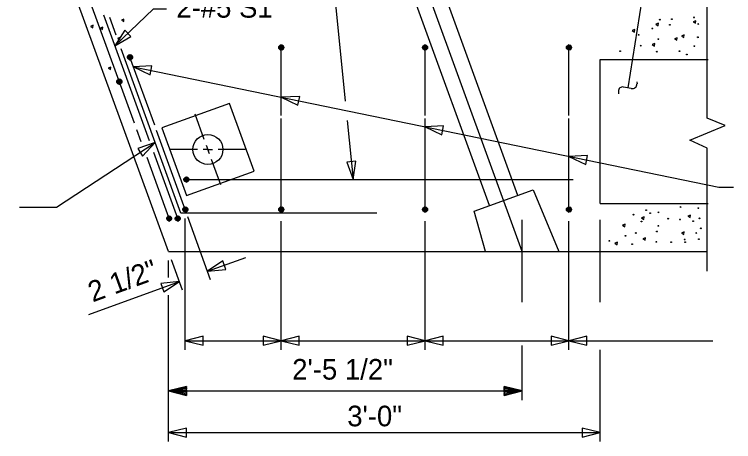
# Model space of a CAD drawing. Extents: x -408 to -23, y -15 to 117.
# Drawn here: x -115.169 to -110.17, y 40.166 to 43.132 of the extents above; entities that cross this region are included whole.
import ezdxf

# ---------------------------------------------------------------- set-up
doc = ezdxf.new("R2010")
doc.units = 0
for name, color, linetype in [('Arrowhead Terminators CELL', 7, 'Continuous'), ('Dimension Lines', 7, 'Continuous'), ('Mis Center Lines', 7, 'Continuous'), ('Rebar Lines', 7, 'Continuous'), ('Sup Concrete Girder Lines', 7, 'Continuous'), ('Sup Cored Slab Unit', 7, 'Continuous'), ('Text', 7, 'Continuous')]:
    doc.layers.add(name, color=color, linetype=linetype)

msp = doc.modelspace()

# ---------------------------------------------------------------- linework, layer by layer
at = {"layer": 'Arrowhead Terminators CELL'}
for points in [[(-114.471, 42.9146), (-114.359, 42.9782), (-114.402, 43.0235)], [(-114.3417, 42.7692), (-114.2256, 42.7134), (-114.213, 42.7746)], [(-113.3141, 42.5577), (-113.198, 42.5019), (-113.1854, 42.5632)], [(-112.3141, 42.352), (-112.198, 42.2962), (-112.1854, 42.3574)], [(-114.19, 42.2424), (-114.3117, 42.2), (-114.2774, 42.1478)], [(-111.3141, 42.1462), (-111.198, 42.0904), (-111.1854, 42.1516)], [(-112.8146, 41.9859), (-112.7959, 42.1134), (-112.8581, 42.1072)], [(-113.8264, 41.3484), (-113.6982, 41.3618), (-113.7196, 41.4206)], [(-114.0221, 41.2772), (-114.1502, 41.2638), (-114.1289, 41.2051)], [(-113.9808, 40.8667), (-113.8558, 40.8355), (-113.8558, 40.898)], [(-113.3141, 40.8667), (-113.4391, 40.898), (-113.4391, 40.8355)], [(-113.3141, 40.8667), (-113.1891, 40.8355), (-113.1891, 40.898)], [(-112.3141, 40.8667), (-112.4391, 40.898), (-112.4391, 40.8355)], [(-112.3141, 40.8667), (-112.1891, 40.8355), (-112.1891, 40.898)], [(-111.3141, 40.8667), (-111.4391, 40.898), (-111.4391, 40.8355)], [(-111.3141, 40.8667), (-111.1891, 40.8355), (-111.1891, 40.898)], [(-114.098, 40.229), (-113.973, 40.1978), (-113.973, 40.2603)], [(-111.098, 40.229), (-111.223, 40.2603), (-111.223, 40.1978)]]:
    msp.add_lwpolyline(points, close=True, dxfattribs=at)
at = {"layer": 'Dimension Lines'}
for p, q in [((-112.9761, 43.6051), (-112.8687, 42.5288)), ((-110.8417, 42.6647), (-110.8415, 42.6509)), ((-110.9699, 42.5983), (-110.9704, 42.58)), ((-110.8812, 42.6188), (-110.9357, 42.6275)), ((-113.8488, 42.2631), (-113.913, 42.4392)), ((-112.8554, 42.3948), (-112.8146, 41.9859)), ((-113.8954, 42.1945), (-114.0829, 42.1944)), ((-113.5647, 42.1944), (-113.7523, 42.1944)), ((-113.7347, 41.9496), (-113.7989, 42.1258)), ((-113.9808, 40.8037), (-113.9808, 41.715)), ((-113.805, 41.2897), (-113.9637, 41.7261)), ((-113.3141, 40.8037), (-113.3141, 41.6974)), ((-112.3141, 40.8037), (-112.3141, 41.6974)), ((-111.6396, 41.134), (-111.6396, 41.7067)), ((-111.3141, 40.8037), (-111.3141, 41.6974)), ((-111.098, 41.134), (-111.098, 41.7067)), ((-113.8264, 41.3484), (-113.561, 41.4451)), ((-114.098, 41.3057), (-114.098, 41.4234)), ((-114.0007, 41.2184), (-114.0766, 41.4271)), ((-114.6521, 41.0479), (-114.0221, 41.2772)), ((-114.098, 40.166), (-114.098, 41.1822)), ((-113.9808, 40.8667), (-113.3141, 40.8667)), ((-113.3141, 40.8667), (-112.3141, 40.8667)), ((-112.3141, 40.8667), (-111.3141, 40.8667)), ((-111.3141, 40.8667), (-110.3141, 40.8667)), ((-111.6396, 40.4548), (-111.6396, 40.8332)), ((-111.098, 40.166), (-111.098, 40.8042)), ((-114.098, 40.5178), (-111.6396, 40.5178)), ((-114.098, 40.229), (-111.098, 40.229))]:
    msp.add_line(p, q, dxfattribs=at)
for points in [[(-110.9035, 42.6224), (-110.7245, 43.7456), (-110.8716, 43.7456)], [(-114.471, 42.9146), (-114.2026, 43.1701), (-114.1117, 43.1701)], [(-114.3417, 42.7692), (-110.272, 41.9318), (-110.17, 41.9318)], [(-115.1321, 41.7927), (-114.8761, 41.7927), (-114.19, 42.2424)], [(-113.8347, 42.2239), (-113.8238, 42.1944), (-113.8554, 42.1943)], [(-113.8128, 42.1647), (-113.8235, 42.1942), (-113.7921, 42.1943)], [(-113.973, 40.5178), (-113.973, 40.5115), (-114.098, 40.5178), (-113.973, 40.5053), (-113.973, 40.499), (-114.098, 40.5178), (-113.973, 40.4928), (-113.973, 40.4865), (-114.098, 40.5178), (-113.973, 40.549), (-113.973, 40.5428), (-114.098, 40.5178), (-113.973, 40.5365), (-113.973, 40.5303), (-114.098, 40.5178), (-113.973, 40.524), (-113.973, 40.4865), (-113.973, 40.549), (-114.098, 40.5178), (-113.973, 40.4865)], [(-111.7646, 40.5178), (-111.7646, 40.524), (-111.6396, 40.5178), (-111.7646, 40.5303), (-111.7646, 40.5365), (-111.6396, 40.5178), (-111.7646, 40.5428), (-111.7646, 40.549), (-111.6396, 40.5178), (-111.7646, 40.4865), (-111.7646, 40.4928), (-111.6396, 40.5178), (-111.7646, 40.499), (-111.7646, 40.5053), (-111.6396, 40.5178), (-111.7646, 40.5115), (-111.7646, 40.549), (-111.7646, 40.4865), (-111.6396, 40.5178), (-111.7646, 40.549)]]:
    msp.add_lwpolyline(points, dxfattribs=at)
for centre, radius, start, end in [((-110.8728, 42.6487), 0.0311, 254.3783, 4.1772), ((-110.9422, 42.6008), 0.0276, 76.8232, 185.1088)]:
    msp.add_arc(centre, radius, start, end, dxfattribs=at)
at = {"layer": 'Mis Center Lines'}
msp.add_line((-111.6396, 41.4859), (-112.79, 44.6464), dxfattribs=at)
at = {"layer": 'Rebar Lines'}
for p, q in [((-114.3337, 42.3769), (-114.6366, 43.209)), ((-114.2294, 42.2549), (-114.5465, 43.1261)), ((-114.461, 42.987), (-114.5057, 43.1097)), ((-114.0113, 41.7515), (-114.4267, 42.8928)), ((-113.3141, 42.4309), (-113.3141, 42.9025)), ((-112.3141, 42.4309), (-112.3141, 42.9025)), ((-111.3141, 42.4309), (-111.3141, 42.9025)), ((-114.1935, 42.3621), (-114.3656, 42.8347)), ((-113.3141, 41.7775), (-113.3141, 42.4091)), ((-112.3141, 41.7775), (-112.3141, 42.4091)), ((-111.3141, 41.7775), (-111.3141, 42.4091)), ((-114.2868, 42.2482), (-114.317, 42.3312)), ((-113.9808, 41.7775), (-114.1806, 42.3264)), ((-114.0928, 41.715), (-114.2467, 42.138)), ((-114.033, 41.715), (-114.2, 42.1738)), ((-113.9728, 41.9859), (-111.2853, 41.9859)), ((-112.6503, 41.7515), (-114.0113, 41.7515))]:
    msp.add_line(p, q, dxfattribs=at)
for points in [[(-113.3317, 42.9025), (-113.3304, 42.9092), (-113.3266, 42.915), (-113.3209, 42.9188), (-113.3141, 42.9201), (-113.3074, 42.9188), (-113.3017, 42.915), (-113.2979, 42.9093), (-113.2965, 42.9025), (-113.2979, 42.8958), (-113.3017, 42.8901), (-113.3074, 42.8862), (-113.3141, 42.8849), (-113.3209, 42.8862), (-113.3266, 42.89), (-113.3304, 42.8957), (-113.3317, 42.9025), (-113.3141, 42.9025), (-113.2965, 42.9025), (-113.2979, 42.9093), (-113.3141, 42.9025), (-113.3017, 42.915), (-113.3074, 42.9188), (-113.3141, 42.9025), (-113.3141, 42.9201), (-113.3209, 42.9188), (-113.3141, 42.9025), (-113.3266, 42.915), (-113.3304, 42.9092), (-113.3141, 42.9025), (-113.3304, 42.8957), (-113.3266, 42.89), (-113.3141, 42.9025), (-113.3209, 42.8862), (-113.3141, 42.8849), (-113.3141, 42.9025), (-113.3074, 42.8862), (-113.3017, 42.8901), (-113.3141, 42.9025), (-113.2979, 42.8958)], [(-112.3317, 42.9025), (-112.3304, 42.9092), (-112.3266, 42.915), (-112.3209, 42.9188), (-112.3141, 42.9201), (-112.3074, 42.9188), (-112.3017, 42.915), (-112.2979, 42.9093), (-112.2965, 42.9025), (-112.2979, 42.8958), (-112.3017, 42.8901), (-112.3074, 42.8862), (-112.3141, 42.8849), (-112.3209, 42.8862), (-112.3266, 42.89), (-112.3304, 42.8957), (-112.3317, 42.9025), (-112.3141, 42.9025), (-112.2965, 42.9025), (-112.2979, 42.9093), (-112.3141, 42.9025), (-112.3017, 42.915), (-112.3074, 42.9188), (-112.3141, 42.9025), (-112.3141, 42.9201), (-112.3209, 42.9188), (-112.3141, 42.9025), (-112.3266, 42.915), (-112.3304, 42.9092), (-112.3141, 42.9025), (-112.3304, 42.8957), (-112.3266, 42.89), (-112.3141, 42.9025), (-112.3209, 42.8862), (-112.3141, 42.8849), (-112.3141, 42.9025), (-112.3074, 42.8862), (-112.3017, 42.8901), (-112.3141, 42.9025), (-112.2979, 42.8958)], [(-111.3317, 42.9025), (-111.3304, 42.9092), (-111.3266, 42.915), (-111.3209, 42.9188), (-111.3141, 42.9201), (-111.3074, 42.9188), (-111.3017, 42.915), (-111.2979, 42.9093), (-111.2965, 42.9025), (-111.2979, 42.8958), (-111.3017, 42.8901), (-111.3074, 42.8862), (-111.3141, 42.8849), (-111.3209, 42.8862), (-111.3266, 42.89), (-111.3304, 42.8957), (-111.3317, 42.9025), (-111.3141, 42.9025), (-111.2965, 42.9025), (-111.2979, 42.9093), (-111.3141, 42.9025), (-111.3017, 42.915), (-111.3074, 42.9188), (-111.3141, 42.9025), (-111.3141, 42.9201), (-111.3209, 42.9188), (-111.3141, 42.9025), (-111.3266, 42.915), (-111.3304, 42.9092), (-111.3141, 42.9025), (-111.3304, 42.8957), (-111.3266, 42.89), (-111.3141, 42.9025), (-111.3209, 42.8862), (-111.3141, 42.8849), (-111.3141, 42.9025), (-111.3074, 42.8862), (-111.3017, 42.8901), (-111.3141, 42.9025), (-111.2979, 42.8958)], [(-114.3829, 42.8317), (-114.3828, 42.8385), (-114.3801, 42.8448), (-114.3751, 42.8496), (-114.3687, 42.852), (-114.3618, 42.8519), (-114.3555, 42.8491), (-114.3507, 42.8442), (-114.3482, 42.8378), (-114.3484, 42.8309), (-114.3512, 42.8246), (-114.3561, 42.8199), (-114.3625, 42.8174), (-114.3694, 42.8175), (-114.3757, 42.8203), (-114.3805, 42.8252), (-114.3829, 42.8317), (-114.3656, 42.8347), (-114.3482, 42.8378), (-114.3507, 42.8442), (-114.3656, 42.8347), (-114.3555, 42.8491), (-114.3618, 42.8519), (-114.3656, 42.8347), (-114.3687, 42.852), (-114.3751, 42.8496), (-114.3656, 42.8347), (-114.3801, 42.8448), (-114.3828, 42.8385), (-114.3656, 42.8347), (-114.3805, 42.8252), (-114.3757, 42.8203), (-114.3656, 42.8347), (-114.3694, 42.8175), (-114.3625, 42.8174), (-114.3656, 42.8347), (-114.3561, 42.8199), (-114.3512, 42.8246), (-114.3656, 42.8347), (-114.3484, 42.8309)], [(-114.456, 42.6623), (-114.4559, 42.6691), (-114.4531, 42.6754), (-114.4481, 42.6802), (-114.4417, 42.6827), (-114.4349, 42.6826), (-114.4285, 42.6798), (-114.4238, 42.6748), (-114.4213, 42.6684), (-114.4215, 42.6615), (-114.4242, 42.6552), (-114.4292, 42.6504), (-114.4356, 42.6479), (-114.4425, 42.6481), (-114.4488, 42.6508), (-114.4535, 42.6558), (-114.456, 42.6623), (-114.4387, 42.6653), (-114.4213, 42.6684), (-114.4238, 42.6748), (-114.4387, 42.6653), (-114.4285, 42.6798), (-114.4349, 42.6826), (-114.4387, 42.6653), (-114.4417, 42.6827), (-114.4481, 42.6802), (-114.4387, 42.6653), (-114.4531, 42.6754), (-114.4559, 42.6691), (-114.4387, 42.6653), (-114.4535, 42.6558), (-114.4488, 42.6508), (-114.4387, 42.6653), (-114.4425, 42.6481), (-114.4356, 42.6479), (-114.4387, 42.6653), (-114.4292, 42.6504), (-114.4242, 42.6552), (-114.4387, 42.6653), (-114.4215, 42.6615)], [(-113.9901, 41.9828), (-113.99, 41.9897), (-113.9872, 41.996), (-113.9823, 42.0008), (-113.9758, 42.0032), (-113.969, 42.0031), (-113.9627, 42.0003), (-113.958, 41.9954), (-113.9555, 41.989), (-113.9556, 41.9821), (-113.9584, 41.9758), (-113.9633, 41.971), (-113.9697, 41.9685), (-113.9766, 41.9687), (-113.9829, 41.9714), (-113.9877, 41.9764), (-113.9901, 41.9828), (-113.9728, 41.9859), (-113.9555, 41.989), (-113.958, 41.9954), (-113.9728, 41.9859), (-113.9627, 42.0003), (-113.969, 42.0031), (-113.9728, 41.9859), (-113.9758, 42.0032), (-113.9823, 42.0008), (-113.9728, 41.9859), (-113.9872, 41.996), (-113.99, 41.9897), (-113.9728, 41.9859), (-113.9877, 41.9764), (-113.9829, 41.9714), (-113.9728, 41.9859), (-113.9766, 41.9687), (-113.9697, 41.9685), (-113.9728, 41.9859), (-113.9633, 41.971), (-113.9584, 41.9758), (-113.9728, 41.9859), (-113.9556, 41.9821)], [(-113.9981, 41.7744), (-113.998, 41.7813), (-113.9953, 41.7876), (-113.9903, 41.7924), (-113.9839, 41.7949), (-113.977, 41.7948), (-113.9707, 41.7919), (-113.966, 41.787), (-113.9634, 41.7806), (-113.9637, 41.7737), (-113.9664, 41.7674), (-113.9713, 41.7626), (-113.9777, 41.7601), (-113.9846, 41.7603), (-113.9909, 41.763), (-113.9957, 41.768), (-113.9981, 41.7744), (-113.9808, 41.7775), (-113.9634, 41.7806), (-113.966, 41.787), (-113.9808, 41.7775), (-113.9707, 41.7919), (-113.977, 41.7948), (-113.9808, 41.7775), (-113.9839, 41.7949), (-113.9903, 41.7924), (-113.9808, 41.7775), (-113.9953, 41.7876), (-113.998, 41.7813), (-113.9808, 41.7775), (-113.9957, 41.768), (-113.9909, 41.763), (-113.9808, 41.7775), (-113.9846, 41.7603), (-113.9777, 41.7601), (-113.9808, 41.7775), (-113.9713, 41.7626), (-113.9664, 41.7674), (-113.9808, 41.7775), (-113.9637, 41.7737)], [(-113.3317, 41.7775), (-113.3304, 41.7842), (-113.3266, 41.79), (-113.3209, 41.7938), (-113.3141, 41.7951), (-113.3074, 41.7938), (-113.3017, 41.79), (-113.2979, 41.7843), (-113.2965, 41.7775), (-113.2979, 41.7708), (-113.3017, 41.7651), (-113.3074, 41.7612), (-113.3141, 41.7599), (-113.3209, 41.7612), (-113.3266, 41.765), (-113.3304, 41.7707), (-113.3317, 41.7775), (-113.3141, 41.7775), (-113.2965, 41.7775), (-113.2979, 41.7843), (-113.3141, 41.7775), (-113.3017, 41.79), (-113.3074, 41.7938), (-113.3141, 41.7775), (-113.3141, 41.7951), (-113.3209, 41.7938), (-113.3141, 41.7775), (-113.3266, 41.79), (-113.3304, 41.7842), (-113.3141, 41.7775), (-113.3304, 41.7707), (-113.3266, 41.765), (-113.3141, 41.7775), (-113.3209, 41.7612), (-113.3141, 41.7599), (-113.3141, 41.7775), (-113.3074, 41.7612), (-113.3017, 41.7651), (-113.3141, 41.7775), (-113.2979, 41.7708)], [(-112.3317, 41.7775), (-112.3304, 41.7842), (-112.3266, 41.79), (-112.3209, 41.7938), (-112.3141, 41.7951), (-112.3074, 41.7938), (-112.3017, 41.79), (-112.2979, 41.7843), (-112.2965, 41.7775), (-112.2979, 41.7708), (-112.3017, 41.7651), (-112.3074, 41.7612), (-112.3141, 41.7599), (-112.3209, 41.7612), (-112.3266, 41.765), (-112.3304, 41.7707), (-112.3317, 41.7775), (-112.3141, 41.7775), (-112.2965, 41.7775), (-112.2979, 41.7843), (-112.3141, 41.7775), (-112.3017, 41.79), (-112.3074, 41.7938), (-112.3141, 41.7775), (-112.3141, 41.7951), (-112.3209, 41.7938), (-112.3141, 41.7775), (-112.3266, 41.79), (-112.3304, 41.7842), (-112.3141, 41.7775), (-112.3304, 41.7707), (-112.3266, 41.765), (-112.3141, 41.7775), (-112.3209, 41.7612), (-112.3141, 41.7599), (-112.3141, 41.7775), (-112.3074, 41.7612), (-112.3017, 41.7651), (-112.3141, 41.7775), (-112.2979, 41.7708)], [(-111.3317, 41.7775), (-111.3304, 41.7842), (-111.3266, 41.79), (-111.3209, 41.7938), (-111.3141, 41.7951), (-111.3074, 41.7938), (-111.3017, 41.79), (-111.2979, 41.7843), (-111.2965, 41.7775), (-111.2979, 41.7708), (-111.3017, 41.7651), (-111.3074, 41.7612), (-111.3141, 41.7599), (-111.3209, 41.7612), (-111.3266, 41.765), (-111.3304, 41.7707), (-111.3317, 41.7775), (-111.3141, 41.7775), (-111.2965, 41.7775), (-111.2979, 41.7843), (-111.3141, 41.7775), (-111.3017, 41.79), (-111.3074, 41.7938), (-111.3141, 41.7775), (-111.3141, 41.7951), (-111.3209, 41.7938), (-111.3141, 41.7775), (-111.3266, 41.79), (-111.3304, 41.7842), (-111.3141, 41.7775), (-111.3304, 41.7707), (-111.3266, 41.765), (-111.3141, 41.7775), (-111.3209, 41.7612), (-111.3141, 41.7599), (-111.3141, 41.7775), (-111.3074, 41.7612), (-111.3017, 41.7651), (-111.3141, 41.7775), (-111.2979, 41.7708)], [(-114.1101, 41.7119), (-114.11, 41.7188), (-114.1072, 41.7251), (-114.1023, 41.7299), (-114.0958, 41.7324), (-114.089, 41.7323), (-114.0827, 41.7294), (-114.078, 41.7245), (-114.0755, 41.7181), (-114.0756, 41.7112), (-114.0784, 41.7049), (-114.0833, 41.7001), (-114.0897, 41.6976), (-114.0966, 41.6978), (-114.1029, 41.7005), (-114.1077, 41.7055), (-114.1101, 41.7119), (-114.0928, 41.715), (-114.0755, 41.7181), (-114.078, 41.7245), (-114.0928, 41.715), (-114.0827, 41.7294), (-114.089, 41.7323), (-114.0928, 41.715), (-114.0958, 41.7324), (-114.1023, 41.7299), (-114.0928, 41.715), (-114.1072, 41.7251), (-114.11, 41.7188), (-114.0928, 41.715), (-114.1077, 41.7055), (-114.1029, 41.7005), (-114.0928, 41.715), (-114.0966, 41.6978), (-114.0897, 41.6976), (-114.0928, 41.715), (-114.0833, 41.7001), (-114.0784, 41.7049), (-114.0928, 41.715), (-114.0756, 41.7112)], [(-114.0504, 41.712), (-114.0502, 41.7188), (-114.0475, 41.7251), (-114.0425, 41.7299), (-114.036, 41.7324), (-114.0292, 41.7323), (-114.0229, 41.7294), (-114.0182, 41.7245), (-114.0157, 41.7181), (-114.0158, 41.7113), (-114.0186, 41.705), (-114.0235, 41.7002), (-114.03, 41.6977), (-114.0368, 41.6978), (-114.0431, 41.7006), (-114.0479, 41.7055), (-114.0504, 41.712), (-114.033, 41.715), (-114.0157, 41.7181), (-114.0182, 41.7245), (-114.033, 41.715), (-114.0229, 41.7294), (-114.0292, 41.7323), (-114.033, 41.715), (-114.036, 41.7324), (-114.0425, 41.7299), (-114.033, 41.715), (-114.0475, 41.7251), (-114.0502, 41.7188), (-114.033, 41.715), (-114.0479, 41.7055), (-114.0431, 41.7006), (-114.033, 41.715), (-114.0368, 41.6978), (-114.03, 41.6977), (-114.033, 41.715), (-114.0235, 41.7002), (-114.0186, 41.705), (-114.033, 41.715), (-114.0158, 41.7113)]]:
    msp.add_lwpolyline(points, dxfattribs=at)
at = {"layer": 'Sup Concrete Girder Lines'}
for p, q in [((-111.8664, 41.8044), (-112.8425, 44.4859)), ((-111.6707, 41.8757), (-112.6207, 44.4859)), ((-114.098, 41.4859), (-115.1685, 44.4271)), ((-111.098, 42.8192), (-110.348, 42.8192)), ((-111.098, 41.8192), (-111.098, 42.8192)), ((-111.098, 41.8192), (-110.348, 41.8192)), ((-114.098, 41.4859), (-110.3546, 41.4859))]:
    msp.add_line(p, q, dxfattribs=at)
for points in [[(-110.3546, 42.499), (-110.3546, 43.545), (-110.4739, 43.5996), (-110.2296, 43.7017), (-110.3546, 43.7533), (-110.3546, 44.6213)], [(-114.4083, 43.0828), (-114.4069, 43.1001), (-114.4249, 43.0929), (-114.4083, 43.0828)], [(-110.4341, 43.0712), (-110.4326, 43.0884), (-110.4506, 43.0813), (-110.4341, 43.0712)], [(-114.6229, 43.0391), (-114.6214, 43.0564), (-114.6394, 43.0492), (-114.6229, 43.0391)], [(-114.5553, 43.0272), (-114.5539, 43.0444), (-114.5718, 43.0373), (-114.5553, 43.0272)], [(-110.6938, 43.0533), (-110.6923, 43.0706), (-110.7103, 43.0634), (-110.6938, 43.0533)], [(-110.8583, 43.0098), (-110.8568, 43.027), (-110.8748, 43.0199), (-110.8583, 43.0098)], [(-110.5154, 42.972), (-110.5139, 42.9893), (-110.5319, 42.9821), (-110.5154, 42.972)], [(-114.4362, 42.9557), (-114.4347, 42.9729), (-114.4527, 42.9658), (-114.4362, 42.9557)], [(-110.5649, 42.9523), (-110.5634, 42.9695), (-110.5814, 42.9624), (-110.5649, 42.9523)], [(-110.7195, 42.9126), (-110.7181, 42.9299), (-110.736, 42.9227), (-110.7195, 42.9126)], [(-114.4997, 42.7491), (-114.4982, 42.7663), (-114.5162, 42.7592), (-114.4997, 42.7491)], [(-110.3546, 41.3505), (-110.3546, 42.2032), (-110.4739, 42.2579), (-110.2296, 42.36), (-110.3546, 42.4115), (-110.3546, 42.499)], [(-111.8946, 41.4859), (-111.9741, 41.7652), (-111.563, 41.9149), (-111.3847, 41.4859)], [(-110.4717, 41.7212), (-110.4703, 41.7384), (-110.4882, 41.7313), (-110.4717, 41.7212)], [(-110.7929, 41.7093), (-110.7914, 41.7266), (-110.8094, 41.7194), (-110.7929, 41.7093)], [(-110.9257, 41.6578), (-110.9242, 41.675), (-110.9422, 41.6679), (-110.9257, 41.6578)], [(-110.5154, 41.6043), (-110.5139, 41.6215), (-110.5319, 41.6144), (-110.5154, 41.6043)], [(-110.9792, 41.5329), (-110.9778, 41.5502), (-110.9957, 41.543), (-110.9792, 41.5329)], [(-110.785, 41.5646), (-110.7835, 41.5819), (-110.8015, 41.5748), (-110.785, 41.5646)]]:
    msp.add_lwpolyline(points, dxfattribs=at)
for centre, radius in [((-110.6831, 43.0956), 0.00273), ((-110.5999, 43.0996), 0.00273), ((-110.4452, 43.1115), 0.00273), ((-110.6137, 43.0599), 0.00273), ((-110.4155, 43.0659), 0.00273), ((-110.8298, 42.9906), 0.00273), ((-110.7346, 43.0342), 0.00273), ((-110.693, 42.9608), 0.00273), ((-110.4194, 42.9747), 0.00273), ((-110.4175, 42.9727), 0.00273), ((-110.8159, 42.9152), 0.00273), ((-110.4432, 42.9112), 0.00273), ((-110.9587, 42.8776), 0.00273), ((-110.7029, 42.8736), 0.00273), ((-110.5463, 42.8776), 0.00273), ((-110.4948, 42.8537), 0.00273), ((-113.8235, 42.1942), 0.1042), ((-110.5384, 41.7952), 0.00273), ((-110.4155, 41.7873), 0.00273), ((-110.8655, 41.7417), 0.00273), ((-110.7782, 41.7734), 0.00273), ((-110.7505, 41.7516), 0.00273), ((-110.693, 41.7576), 0.00273), ((-110.81, 41.6941), 0.00273), ((-110.6256, 41.714), 0.00273), ((-110.5424, 41.708), 0.00273), ((-110.4512, 41.6961), 0.00273), ((-110.4076, 41.7159), 0.00273), ((-110.693, 41.6644), 0.00273), ((-110.3977, 41.6466), 0.00273), ((-110.921, 41.595), 0.00273), ((-110.8496, 41.6148), 0.00273), ((-110.7029, 41.6247), 0.00273), ((-110.4294, 41.6148), 0.00273), ((-111.034, 41.5593), 0.00273), ((-110.8754, 41.5375), 0.00273), ((-110.7069, 41.5534), 0.00273), ((-110.6038, 41.5514), 0.00273), ((-110.5106, 41.5692), 0.00273), ((-110.5067, 41.5514), 0.00273), ((-110.4115, 41.5712), 0.00273)]:
    msp.add_circle(centre, radius, dxfattribs=at)
at = {"layer": 'Sup Cored Slab Unit'}
msp.add_lwpolyline([(-113.6741, 42.5147), (-114.1439, 42.3436), (-113.9729, 41.8738), (-113.5031, 42.0448)], close=True, dxfattribs=at)

# ---------------------------------------------------------------- texts
at = {"layer": 'Text'}
for s, p in [('2-#5 S1', (-114.0431, 43.1094)), ('2\'-5 1/2"', (-113.2376, 40.5965)), ('3\'-0"', (-112.8553, 40.2723))]:
    msp.add_text(s, height=0.14302, dxfattribs=at).set_placement(p)
msp.add_text('2 1/2"', height=0.14302, rotation=19.9967, dxfattribs=at).set_placement((-114.6243, 41.1322))

doc.saveas('drawing.dxf')
